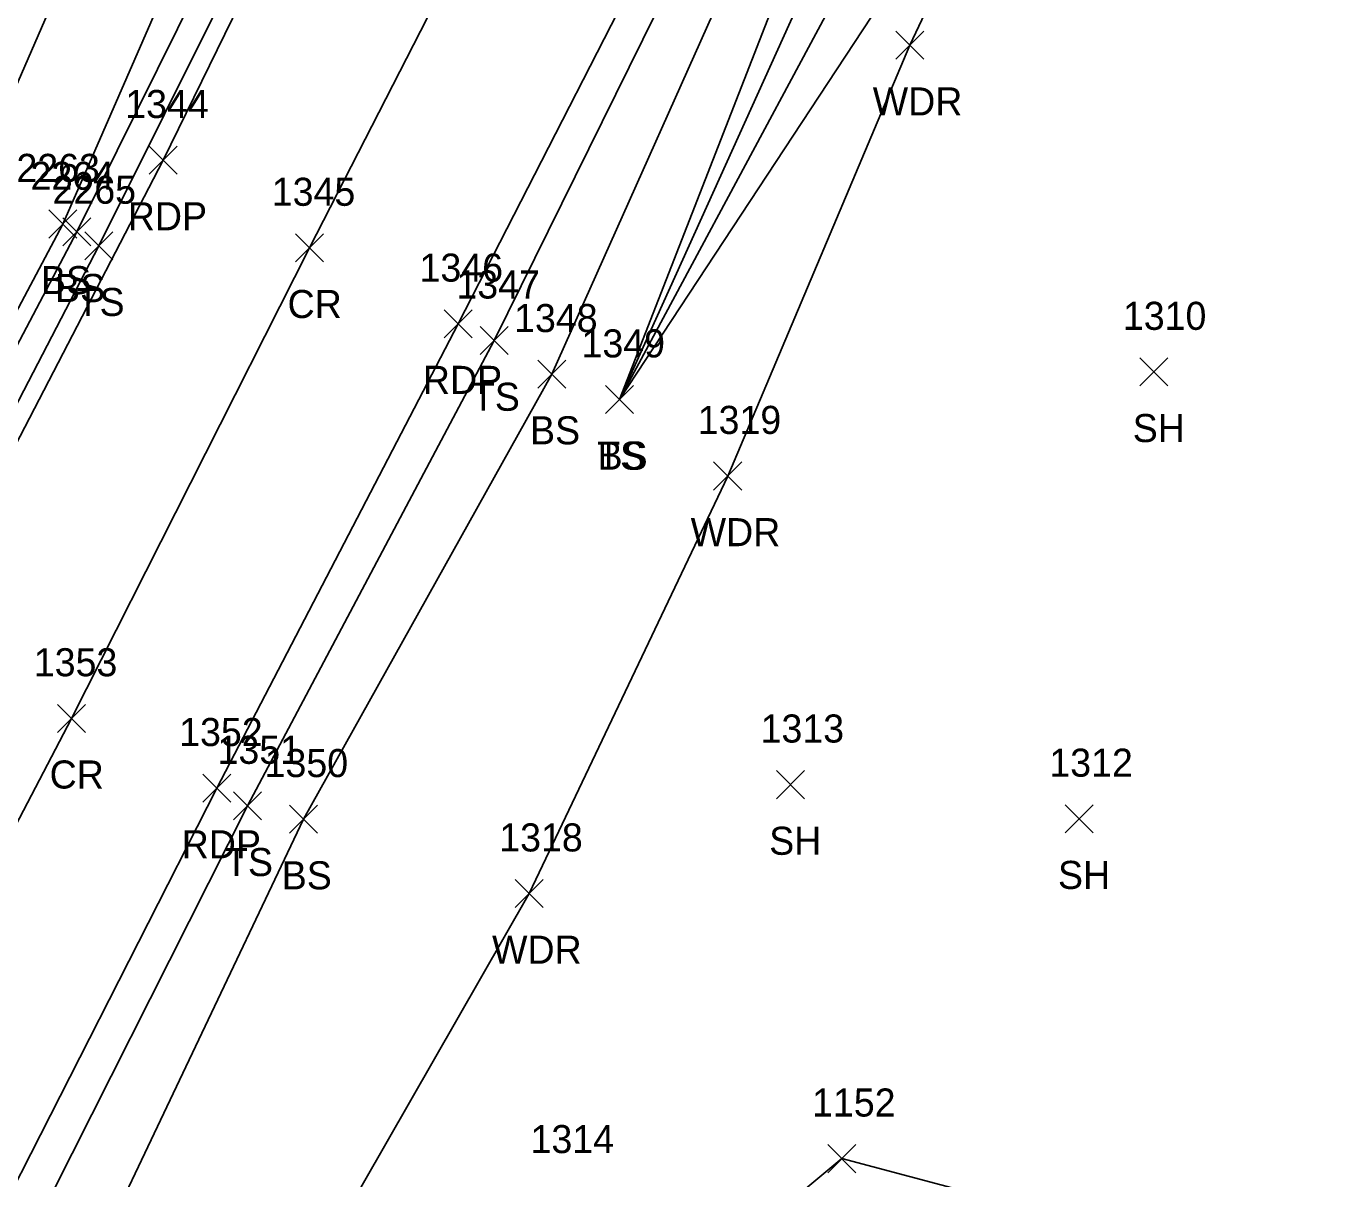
# Model space of a CAD drawing. Extents: x 1885914 to 1887218, y 756253 to 760620.
# Drawn here: x 1886645.8 to 1886739.2, y 760195 to 760277.1 of the extents above; entities that cross this region are included whole.
import ezdxf

# ---------------------------------------------------------------- set-up
doc = ezdxf.new("R2010")
doc.units = 0
for name, color, linetype in [('L_A', 7, 'Continuous'), ('L_I', 7, 'Continuous'), ('L_TIC', 7, 'Continuous'), ('LAWA', 7, 'Continuous'), ('LELB', 7, 'Continuous'), ('P_A', 7, 'Continuous'), ('P_I', 7, 'Continuous'), ('P_TIC', 7, 'Continuous'), ('PET', 7, 'Continuous'), ('PRC', 7, 'Continuous')]:
    doc.layers.add(name, color=color, linetype=linetype)

msp = doc.modelspace()

# ---------------------------------------------------------------- linework, layer by layer
at = {"layer": 'L_TIC'}
for points in [[(1886707.748, 760274.757), (1886709.748, 760276.757)], [(1886709.748, 760274.757), (1886707.748, 760276.757)], [(1886647.397, 760262.018), (1886649.397, 760264.018)], [(1886649.397, 760262.018), (1886647.397, 760264.018)], [(1886648.403, 760261.458), (1886650.403, 760263.458)], [(1886650.403, 760261.458), (1886648.403, 760263.458)], [(1886649.971, 760260.462), (1886651.971, 760262.462)], [(1886651.971, 760260.462), (1886649.971, 760262.462)], [(1886678.137, 760253.706), (1886680.137, 760255.706)], [(1886680.137, 760253.706), (1886678.137, 760255.706)], [(1886682.249, 760251.314), (1886684.249, 760253.314)], [(1886684.249, 760251.314), (1886682.249, 760253.314)], [(1886725.148, 760251.474), (1886727.148, 760253.474)], [(1886727.148, 760251.474), (1886725.148, 760253.474)], [(1886687.061, 760249.51), (1886689.061, 760251.51)], [(1886689.061, 760249.51), (1886687.061, 760251.51)], [(1886687.061, 760249.51), (1886689.061, 760251.51)], [(1886689.061, 760249.51), (1886687.061, 760251.51)], [(1886687.061, 760249.51), (1886689.061, 760251.51)], [(1886689.061, 760249.51), (1886687.061, 760251.51)], [(1886687.061, 760249.51), (1886689.061, 760251.51)], [(1886689.061, 760249.51), (1886687.061, 760251.51)], [(1886694.774, 760244.056), (1886696.774, 760246.056)], [(1886696.774, 760244.056), (1886694.774, 760246.056)], [(1886699.244, 760222.059), (1886701.244, 760224.059)], [(1886701.244, 760222.059), (1886699.244, 760224.059)], [(1886660.548, 760220.541), (1886662.548, 760222.541)], [(1886662.548, 760220.541), (1886660.548, 760222.541)], [(1886664.556, 760219.596), (1886666.556, 760221.596)], [(1886666.556, 760219.596), (1886664.556, 760221.596)], [(1886719.822, 760219.625), (1886721.822, 760221.625)], [(1886721.822, 760219.625), (1886719.822, 760221.625)], [(1886680.622, 760214.296), (1886682.622, 760216.296)], [(1886682.622, 760214.296), (1886680.622, 760216.296)], [(1886702.912, 760195.402), (1886704.912, 760197.402)], [(1886704.912, 760195.402), (1886702.912, 760197.402)]]:
    msp.add_lwpolyline(points, dxfattribs=at)
at = {"layer": 'LAWA'}
for points in [[(1886557.492, 760303.875), (1886591.462, 760287.384), (1886586.596, 760261.317), (1886572.395, 760231.508), (1886560.835, 760204.169), (1886553.529, 760184.951), (1886554.608, 760165.788), (1886555.431, 760150.16), (1886559.733, 760135.931), (1886571.707, 760133.875), (1886584.515, 760154.184), (1886595.308, 760177.701), (1886612.547, 760208.5), (1886627.728, 760237.63), (1886641.554, 760264.816), (1886659.691, 760306.487), (1886641.283, 760308.875), (1886618.53, 760315.267), (1886578.462, 760328.998), (1886533.456, 760348.84), (1886508.343, 760359.001)], [(1886739.178, 760176.379), (1886732.487, 760188.803), (1886703.912, 760196.402), (1886681.182, 760177.484), (1886662.743, 760171.568), (1886662.99, 760182.72), (1886681.622, 760215.296), (1886695.774, 760245.056), (1886708.748, 760275.757), (1886734.574, 760330.315)]]:
    msp.add_lwpolyline(points, dxfattribs=at)
at = {"layer": 'LELB'}
for points in [[(1886566.147, 760118.03), (1886586.712, 760153.389), (1886597.757, 760175.933), (1886614.926, 760207.48), (1886633.427, 760234.813), (1886648.397, 760263.018), (1886665.332, 760301.863), (1886680.817, 760329.686), (1886690.647, 760354.868)], [(1886569.485, 760114.599), (1886588.518, 760152.373), (1886601.13, 760173.249), (1886619.202, 760206.038), (1886634.532, 760234.244), (1886649.403, 760262.458), (1886668.061, 760300.134), (1886683.151, 760328.963), (1886694.248, 760353.247)], [(1886571.834, 760112.637), (1886591.916, 760150.851), (1886603.315, 760171.698), (1886621.882, 760204.85), (1886636.208, 760233.059), (1886650.971, 760261.462), (1886669.739, 760299.131), (1886684.784, 760328.15), (1886696.366, 760352.364)], [(1886725.275, 760338.088), (1886712.33, 760310.283), (1886698.464, 760286.411), (1886683.249, 760252.314), (1886665.556, 760220.596), (1886649.265, 760186.301), (1886631.931, 760155.478), (1886614.955, 760123.769), (1886599.485, 760094.936), (1886586.465, 760070.531), (1886572.038, 760041.069), (1886559.716, 760022.589), (1886545.866, 759996.973), (1886529.407, 759963.137), (1886510.599, 759921.246), (1886501.243, 759900.363), (1886492.686, 759872.906), (1886485.386, 759846.951), (1886480.557, 759824.589), (1886476.3, 759808.266), (1886477.13, 759795.208)], [(1886722.335, 760338.161), (1886708.199, 760311.937), (1886695.499, 760287.882), (1886679.137, 760254.706), (1886661.548, 760221.541), (1886644.914, 760188.523), (1886628.613, 760157.02), (1886611.221, 760125.898), (1886595.573, 760097.053), (1886583.235, 760072.237), (1886569.527, 760041.337), (1886558.979, 760023.45), (1886545.009, 759997.381), (1886527.639, 759964.018), (1886508.852, 759921.989)], [(1886720.755, 760320.964), (1886703.747, 760285.193), (1886688.061, 760250.51)], [(1886720.755, 760320.964), (1886724.232, 760319.074), (1886706.019, 760283.986), (1886688.061, 760250.51)], [(1886727.279, 760320.342), (1886709.119, 760282.505), (1886688.061, 760250.51)], [(1886712.33, 760310.283), (1886701.747, 760285.623), (1886688.061, 760250.51)]]:
    msp.add_lwpolyline(points, dxfattribs=at)
at = {"layer": 'P_TIC'}
for points in [[(1886654.54, 760266.572), (1886656.54, 760268.572)], [(1886656.54, 760266.572), (1886654.54, 760268.572)], [(1886664.98, 760260.316), (1886666.98, 760262.316)], [(1886666.98, 760260.316), (1886664.98, 760262.316)], [(1886675.565, 760254.91), (1886677.565, 760256.91)], [(1886677.565, 760254.91), (1886675.565, 760256.91)], [(1886648.024, 760226.782), (1886650.024, 760228.782)], [(1886650.024, 760226.782), (1886648.024, 760228.782)], [(1886658.381, 760221.808), (1886660.381, 760223.808)], [(1886660.381, 760221.808), (1886658.381, 760223.808)]]:
    msp.add_lwpolyline(points, dxfattribs=at)
at = {"layer": 'PET'}
for points in [[(1886697.38, 760351.344), (1886683.548, 760324.324), (1886670.919, 760298.997), (1886655.54, 760267.572), (1886637.844, 760233.454), (1886621.762, 760202.258), (1886604.958, 760170.918), (1886588.135, 760139.085), (1886573.727, 760111.629), (1886569.921, 760108.658), (1886558.783, 760086.235), (1886539.061, 760048.095), (1886537.996, 760043.117), (1886529.578, 760026.839), (1886519.947, 760007.47), (1886505.21, 759975.038), (1886485.323, 759931.758)], [(1886719.61, 760339.514), (1886705.929, 760312.964), (1886693.411, 760288.801), (1886676.565, 760255.91), (1886659.381, 760222.808), (1886642.609, 760189.876), (1886625.619, 760158.68), (1886608.905, 760127.1), (1886594.007, 760097.907), (1886581.162, 760073.399), (1886568.003, 760045.025), (1886556.596, 760025.444), (1886542.605, 759998.542), (1886526.138, 759964.92), (1886507.071, 759922.754)]]:
    msp.add_lwpolyline(points, dxfattribs=at)
at = {"layer": 'PRC'}
msp.add_lwpolyline([(1886708.511, 760345.163), (1886695.269, 760318.5), (1886682.3, 760293.202), (1886665.98, 760261.316), (1886649.024, 760227.782), (1886632.442, 760196.03), (1886615.486, 760164.092), (1886599.17, 760133.157), (1886583.217, 760103.131), (1886570.574, 760078.827), (1886555.848, 760051.114), (1886540.619, 760021), (1886531.872, 760002.722), (1886516.053, 759969.427), (1886496.99, 759926.688)], dxfattribs=at)

# ---------------------------------------------------------------- texts
at = {"layer": 'L_A'}
for s, p in [('WDR', (1886706.11, 760270.757)), ('BS', (1886646.838, 760258.018)), ('BS', (1886647.844, 760257.458)), ('TS', (1886649.38, 760256.462)), ('TS', (1886677.546, 760249.706)), ('BS', (1886681.69, 760247.314)), ('SH', (1886724.637, 760247.474)), ('TS', (1886686.471, 760245.51)), ('TS', (1886686.471, 760245.51)), ('BS', (1886686.502, 760245.51)), ('BS', (1886686.502, 760245.51)), ('WDR', (1886693.136, 760240.056)), ('SH', (1886698.732, 760218.059)), ('TS', (1886659.957, 760216.541)), ('BS', (1886663.997, 760215.596)), ('SH', (1886719.31, 760215.625)), ('WDR', (1886678.984, 760210.296))]:
    msp.add_text(s, height=2, dxfattribs=at).set_placement(p)
at = {"layer": 'L_I'}
for s, p in [('2263', (1886645.09, 760266.018)), ('2264', (1886646.096, 760265.458)), ('2265', (1886647.664, 760264.462)), ('1347', (1886676.444, 760257.706)), ('1348', (1886680.556, 760255.314)), ('1310', (1886723.936, 760255.474)), ('1349', (1886685.36, 760253.51)), ('1349', (1886685.36, 760253.51)), ('1349', (1886685.36, 760253.51)), ('1349', (1886685.36, 760253.51)), ('1319', (1886693.64, 760248.056)), ('1313', (1886698.118, 760226.059)), ('1351', (1886659.422, 760224.541)), ('1350', (1886662.776, 760223.596)), ('1312', (1886718.696, 760223.625)), ('1318', (1886679.496, 760218.296)), ('1152', (1886701.786, 760199.402)), ('1314', (1886681.726, 760196.796))]:
    msp.add_text(s, height=2, dxfattribs=at).set_placement(p)
at = {"layer": 'P_A'}
for s, p in [('RDP', (1886653.028, 760262.572)), ('CR', (1886664.413, 760256.316)), ('RDP', (1886674.053, 760250.91)), ('CR', (1886647.457, 760222.782)), ('RDP', (1886656.87, 760217.808))]:
    msp.add_text(s, height=2, dxfattribs=at).set_placement(p)
at = {"layer": 'P_I'}
for s, p in [('1344', (1886652.847, 760270.572)), ('1345', (1886663.287, 760264.316)), ('1346', (1886673.817, 760258.91)), ('1353', (1886646.331, 760230.782)), ('1352', (1886656.688, 760225.808))]:
    msp.add_text(s, height=2, dxfattribs=at).set_placement(p)

doc.saveas('drawing.dxf')
